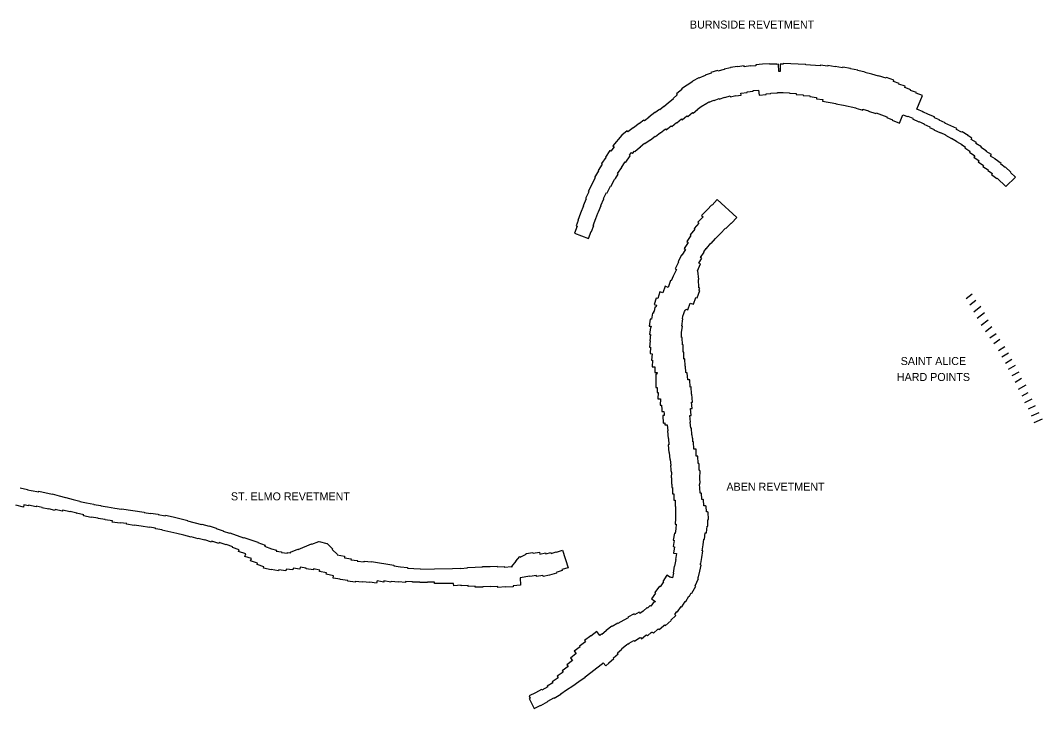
# Model space of a CAD drawing. Extents: x 2650582 to 3923188, y 277893 to 989177.
# Drawn here: x 3390842 to 3411271, y 583622 to 597381 of the extents above; entities that cross this region are included whole.
import ezdxf

# ---------------------------------------------------------------- set-up
doc = ezdxf.new("R2010")
doc.units = 0
doc.layers.add('Level 3', color=7, linetype='Continuous')

msp = doc.modelspace()

# ---------------------------------------------------------------- linework, layer by layer
at = {"layer": 'Level 3'}
for p, q in [((3409746, 591820), (3409864, 591911)), ((3409818, 591692), (3409940, 591791)), ((3409900, 591557), (3410040, 591668)), ((3409966, 591430), (3410109, 591539)), ((3410046, 591290), (3410186, 591392)), ((3410129, 591164), (3410259, 591264)), ((3410220, 591035), (3410345, 591120)), ((3410296, 590920), (3410415, 591006)), ((3410390, 590782), (3410518, 590864)), ((3410455, 590652), (3410590, 590738)), ((3410527, 590525), (3410659, 590607)), ((3410590, 590410), (3410730, 590488)), ((3410661, 590281), (3410805, 590354)), ((3410722, 590147), (3410851, 590227)), ((3410791, 590010), (3410943, 590097)), ((3410862, 589878), (3410986, 589939)), ((3410918, 589740), (3411062, 589812)), ((3410990, 589614), (3411131, 589682)), ((3411051, 589476), (3411201, 589541)), ((3411105, 589342), (3411271, 589412))]:
    msp.add_line(p, q, dxfattribs=at)
for points in [[(3405537, 596493), (3405539, 596476), (3405433, 596464), (3405432, 596470), (3405310, 596456), (3405308, 596471), (3405175, 596456), (3405175, 596460), (3405033, 596441), (3405033, 596436), (3404906, 596407), (3404907, 596398), (3404778, 596366), (3404775, 596379), (3404641, 596338), (3404645, 596325), (3404528, 596287), (3404530, 596282), (3404401, 596227), (3404400, 596230), (3404276, 596164), (3404279, 596157), (3404171, 596087), (3404170, 596089), (3404054, 596010), (3404058, 596001), (3403956, 595912), (3403970, 595895), (3403888, 595823), (3403894, 595816), (3403785, 595729), (3403787, 595727), (3403703, 595655), (3403700, 595658), (3403624, 595591), (3403615, 595603), (3403522, 595534), (3403519, 595537), (3403399, 595448), (3403403, 595442), (3403316, 595375), (3403304, 595389), (3403212, 595317), (3403209, 595321), (3403093, 595233), (3403091, 595236), (3402985, 595151), (3402970, 595171), (3402864, 595084), (3402861, 595086), (3402685, 594872)], [(3408290, 596159), (3408300, 596188), (3408153, 596239), (3408148, 596227), (3407995, 596271), (3407994, 596268), (3407859, 596307), (3407858, 596303), (3407721, 596339), (3407723, 596345), (3407576, 596380), (3407577, 596386), (3407431, 596415), (3407431, 596419), (3407278, 596448), (3407275, 596435), (3407129, 596461), (3407128, 596455), (3406979, 596478), (3406977, 596469), (3406829, 596485), (3406827, 596470), (3406538, 596492), (3406538, 596501), (3406089, 596517), (3406089, 596503), (3406028, 596504), (3406028, 596361), (3405997, 596361), (3405996, 596503), (3405957, 596502), (3405957, 596509), (3405816, 596505), (3405815, 596511), (3405676, 596506), (3405675, 596509), (3405537, 596493)], [(3410540, 594060), (3410729, 594245), (3410631, 594343), (3410635, 594347), (3410531, 594444), (3410525, 594438), (3410435, 594510), (3410444, 594522), (3410321, 594608), (3410325, 594615), (3410233, 594670), (3410251, 594697), (3410147, 594760), (3410153, 594768), (3410044, 594840), (3410052, 594852), (3409939, 594923), (3409948, 594937), (3409842, 595002), (3409860, 595029), (3409780, 595079), (3409782, 595081), (3409661, 595155), (3409654, 595145), (3409548, 595202), (3409556, 595217), (3409438, 595275), (3409437, 595272), (3409319, 595327), (3409322, 595334), (3409206, 595387), (3409209, 595393), (3409108, 595436), (3409114, 595451), (3408991, 595501), (3408992, 595503), (3408881, 595552), (3408883, 595556), (3408760, 595605), (3408869, 595877), (3408744, 595925), (3408750, 595940), (3408630, 595980), (3408635, 595994), (3408516, 596038), (3408524, 596064), (3408401, 596107), (3408405, 596119), (3408290, 596159)], [(3403014, 594685), (3403056, 594740), (3403078, 594722), (3403117, 594767), (3403120, 594762), (3403174, 594805), (3403232, 594851), (3403228, 594856), (3403318, 594928), (3403324, 594919), (3403429, 594996), (3403432, 594991), (3403531, 595066), (3403535, 595060), (3403634, 595137), (3403636, 595135), (3403736, 595210), (3403747, 595195), (3403849, 595271), (3403861, 595257), (3403957, 595337), (3403959, 595335), (3404053, 595412), (3404068, 595394), (3404164, 595475), (3404178, 595459), (3404275, 595542), (3404288, 595527), (3404372, 595599), (3404370, 595602), (3404449, 595657), (3404559, 595728), (3404604, 595751), (3404606, 595744), (3404703, 595786), (3404705, 595780), (3404806, 595820), (3404810, 595808), (3404919, 595846), (3404921, 595839), (3405030, 595870), (3405034, 595854), (3405139, 595879), (3405139, 595873), (3405246, 595889), (3405241, 595926), (3405365, 595940), (3405365, 595952), (3405485, 595964), (3405485, 595977), (3405594, 595988)], [(3405594, 595988), (3405606, 595884), (3405745, 595899), (3405744, 595913), (3405839, 595917), (3405839, 595927), (3405971, 595932), (3405970, 595940), (3406084, 595941), (3406084, 595937), (3406215, 595936), (3406215, 595924), (3406345, 595920), (3406344, 595903), (3406486, 595894), (3406485, 595882), (3406621, 595872), (3406620, 595858), (3406756, 595842), (3406752, 595815), (3406876, 595799), (3406871, 595768), (3407137, 595721), (3407136, 595715), (3407293, 595685), (3407294, 595689), (3407539, 595634), (3407536, 595624), (3407677, 595587), (3407682, 595604), (3407791, 595571), (3407789, 595564), (3407937, 595518), (3407942, 595532), (3408161, 595452), (3408156, 595439), (3408269, 595396), (3408266, 595389), (3408411, 595328)], [(3408411, 595328), (3408478, 595494), (3408574, 595458), (3408576, 595465), (3408679, 595424), (3408673, 595410), (3408799, 595355), (3408801, 595358), (3408904, 595314), (3408900, 595304), (3409017, 595252), (3409011, 595238), (3409102, 595199), (3409101, 595195), (3409228, 595134), (3409232, 595141), (3409333, 595090), (3409332, 595088), (3409451, 595023), (3409454, 595027), (3409553, 594970), (3409548, 594962), (3409655, 594901), (3409653, 594897), (3409727, 594853), (3409715, 594835), (3409820, 594765), (3409809, 594750), (3409919, 594675), (3409898, 594644), (3410001, 594572), (3409987, 594551), (3410092, 594480), (3410079, 594460), (3410186, 594392), (3410179, 594381), (3410268, 594321), (3410253, 594301), (3410354, 594218), (3410364, 594229), (3410540, 594060)], [(3402685, 594872), (3402708, 594855), (3402643, 594765), (3402625, 594777), (3402534, 594646), (3402540, 594642), (3402454, 594517), (3402467, 594508), (3402388, 594381), (3402394, 594376), (3402318, 594239), (3402329, 594232), (3402192, 593962), (3402203, 593956), (3402135, 593819), (3402148, 593812), (3402089, 593675), (3402093, 593674), (3402034, 593530), (3402037, 593528), (3401984, 593383), (3401990, 593381), (3401950, 593272), (3401970, 593265), (3401919, 593124)], [(3401919, 593124), (3402196, 593022), (3402247, 593163), (3402257, 593160), (3402300, 593278), (3402287, 593283), (3402339, 593423), (3402341, 593422), (3402383, 593530), (3402393, 593553), (3402449, 593678), (3402441, 593681), (3402505, 593816), (3402496, 593820), (3402557, 593941), (3402567, 593937), (3402634, 594066), (3402645, 594061), (3402718, 594199), (3402734, 594221), (3402791, 594310), (3402777, 594319), (3402859, 594438), (3402853, 594442), (3402928, 594553), (3402941, 594546), (3403031, 594672), (3403014, 594685)], [(3404183, 591597), (3404228, 591731), (3404293, 591709), (3404338, 591843), (3404370, 591832), (3404420, 591979), (3404404, 591985), (3404424, 592027), (3404396, 592041), (3404401, 592041), (3404396, 592199), (3404400, 592200), (3404378, 592373), (3404371, 592376), (3404435, 592511), (3404400, 592528), (3404458, 592625), (3404435, 592639), (3404506, 592749), (3404501, 592752), (3404550, 592823), (3404551, 592821), (3404639, 592925), (3404645, 592920), (3404734, 593021), (3404833, 593123), (3404836, 593121), (3404935, 593225), (3404941, 593218), (3405047, 593328), (3405051, 593324), (3405158, 593443), (3404765, 593798), (3404668, 593690), (3404664, 593694), (3404567, 593593), (3404565, 593595), (3404457, 593482), (3404485, 593455), (3404381, 593348), (3404402, 593328), (3404306, 593220), (3404324, 593204), (3404230, 593092), (3404243, 593081), (3404160, 592961), (3404190, 592941), (3404110, 592819), (3404134, 592803), (3404064, 592687), (3404057, 592691), (3403991, 592551), (3403995, 592549), (3403929, 592415), (3403954, 592403), (3403887, 592266), (3403889, 592265), (3403845, 592175)], [(3403845, 592175), (3403837, 592178), (3403791, 592043), (3403726, 592065), (3403681, 591932), (3403623, 591951), (3403580, 591821), (3403546, 591831), (3403506, 591701), (3403553, 591687), (3403542, 591645), (3403522, 591648), (3403508, 591559), (3403496, 591560), (3403493, 591526), (3403477, 591528), (3403457, 591405), (3403429, 591410), (3403407, 591271)], [(3404229, 589349), (3404232, 589349), (3404221, 589481), (3404246, 589483), (3404234, 589621), (3404265, 589623), (3404257, 589747), (3404273, 589748), (3404262, 589906), (3404257, 589905), (3404246, 590052), (3404229, 590050), (3404219, 590195), (3404180, 590192), (3404171, 590338), (3404146, 590337), (3404146, 590342), (3404144, 590342), (3404137, 590469), (3404128, 590469), (3404119, 590612), (3404102, 590610), (3404098, 590749), (3404090, 590748), (3404087, 590894), (3404072, 590893), (3404070, 591042), (3404053, 591042), (3404057, 591143), (3404075, 591268), (3404061, 591270), (3404080, 591415), (3404072, 591415), (3404082, 591469), (3404101, 591519), (3404104, 591518), (3404116, 591559), (3404126, 591584), (3404130, 591583), (3404142, 591611), (3404183, 591597)], [(3403407, 591271), (3403446, 591265), (3403443, 591239), (3403435, 591240), (3403418, 591101), (3403436, 591099), (3403423, 590975), (3403429, 590975), (3403418, 590850), (3403437, 590849), (3403428, 590719), (3403465, 590717), (3403458, 590587), (3403474, 590586), (3403470, 590457), (3403521, 590455), (3403519, 590341), (3403565, 590341), (3403564, 590307), (3403541, 590306), (3403543, 590181), (3403541, 590181), (3403543, 590041), (3403571, 590042), (3403567, 589940)], [(3403567, 589940), (3403585, 589940), (3403581, 589815), (3403633, 589813), (3403629, 589688), (3403654, 589687), (3403659, 589603), (3403663, 589603), (3403661, 589562), (3403703, 589560), (3403706, 589525), (3403705, 589483), (3403678, 589481), (3403691, 589331)], [(3403691, 589331), (3403718, 589333), (3403721, 589293), (3403770, 589298), (3403780, 589177), (3403775, 589176), (3403787, 589022)], [(3404422, 588229), (3404423, 588229), (3404425, 588378), (3404417, 588378), (3404416, 588397), (3404410, 588397), (3404407, 588440), (3404408, 588518), (3404402, 588518), (3404401, 588524), (3404385, 588523), (3404384, 588670), (3404347, 588669), (3404345, 588806), (3404301, 588806), (3404296, 588954), (3404284, 588953), (3404278, 589029), (3404273, 589029), (3404269, 589097), (3404262, 589097), (3404251, 589227), (3404239, 589226), (3404229, 589349)], [(3403787, 589022), (3403792, 589023), (3403803, 588898), (3403786, 588897), (3403800, 588740), (3403806, 588741), (3403819, 588600), (3403828, 588601), (3403840, 588479), (3403836, 588478), (3403842, 588412), (3403841, 588370), (3403846, 588370), (3403848, 588347), (3403852, 588347), (3403851, 588236), (3403854, 588236), (3403854, 588224), (3403853, 588106), (3403859, 588106)], [(3404431, 586495), (3404435, 586521), (3404439, 586520), (3404460, 586646), (3404458, 586646), (3404479, 586775), (3404470, 586777), (3404487, 586898), (3404487, 586898), (3404502, 587009), (3404512, 587008), (3404526, 587139), (3404552, 587136), (3404565, 587268), (3404580, 587268), (3404578, 587399), (3404596, 587401), (3404586, 587552), (3404573, 587551), (3404573, 587553), (3404556, 587553), (3404546, 587672), (3404534, 587671), (3404534, 587679), (3404504, 587679), (3404493, 587799), (3404477, 587797), (3404477, 587804), (3404463, 587804), (3404453, 587926), (3404442, 587925), (3404442, 587929), (3404427, 587929), (3404423, 588038), (3404421, 588038), (3404417, 588102), (3404420, 588102), (3404420, 588130), (3404426, 588130), (3404422, 588229)], [(3390834, 588038), (3390986, 588001), (3390985, 587996)], [(3390985, 587996), (3391057, 587983), (3391057, 587985), (3391207, 587957), (3391209, 587966), (3391474, 587907), (3391476, 587916), (3391619, 587877), (3391618, 587876), (3391745, 587842), (3391746, 587844), (3391897, 587805), (3391896, 587800), (3392031, 587770), (3392030, 587764), (3392160, 587738), (3392159, 587737), (3392312, 587707), (3392312, 587704), (3392448, 587681), (3392447, 587677), (3392581, 587658), (3392580, 587654), (3392727, 587632), (3392726, 587626), (3392859, 587608), (3392860, 587613), (3393318, 587547), (3393317, 587545), (3393444, 587524), (3393444, 587528), (3393596, 587511), (3393595, 587502), (3393736, 587477), (3393739, 587489), (3393895, 587455), (3393896, 587456), (3394185, 587384), (3394183, 587377), (3394463, 587305), (3394465, 587312), (3394612, 587269), (3394613, 587273), (3394756, 587227), (3394755, 587225), (3394896, 587176), (3394894, 587171), (3395023, 587127), (3395026, 587134)], [(3403859, 588106), (3403859, 588039), (3403875, 588039), (3403875, 587914), (3403903, 587914), (3403903, 587789), (3403925, 587789), (3403926, 587664), (3403937, 587664), (3403937, 587554), (3403934, 587554), (3403934, 587420), (3403928, 587311), (3403951, 587309), (3403939, 587215), (3403940, 587215), (3403925, 587124), (3403914, 587126), (3403889, 586987), (3403909, 586984), (3403887, 586861), (3403914, 586856), (3403893, 586732), (3403953, 586722)], [(3390900, 587648), (3390748, 587686)], [(3394809, 586924), (3394668, 586969), (3394662, 586952), (3394529, 586995), (3394527, 586988), (3394396, 587024), (3394394, 587018), (3394253, 587055), (3394252, 587052), (3394107, 587089), (3394106, 587087), (3393966, 587123), (3393965, 587120), (3393671, 587186), (3393673, 587197), (3393540, 587219), (3393541, 587229), (3393419, 587250), (3393418, 587243), (3393253, 587268), (3393254, 587271), (3393118, 587292), (3393116, 587282), (3392963, 587309), (3392965, 587320), (3392834, 587337), (3392833, 587329), (3392676, 587351), (3392680, 587376), (3392535, 587396), (3392536, 587404), (3392392, 587425), (3392392, 587428), (3392254, 587450), (3392253, 587444), (3392104, 587474), (3392109, 587498), (3391965, 587528), (3391966, 587532), (3391833, 587563), (3391830, 587555), (3391686, 587592), (3391679, 587568), (3391538, 587604), (3391532, 587585), (3391410, 587615), (3391408, 587606), (3391272, 587635), (3391274, 587641), (3391155, 587667), (3391153, 587659), (3391004, 587686), (3391002, 587676), (3390911, 587693), (3390900, 587648)], [(3395026, 587134), (3395302, 587039), (3395304, 587045), (3395588, 586946), (3395587, 586942), (3395730, 586890), (3395722, 586870), (3395861, 586818), (3395859, 586815), (3395959, 586790), (3395955, 586772), (3396059, 586756), (3396058, 586745), (3396178, 586730), (3396181, 586745), (3396248, 586736), (3396242, 586751), (3396389, 586810), (3396391, 586805), (3396660, 586918), (3396664, 586910), (3396807, 586960), (3396808, 586956), (3396810, 586960), (3396965, 586924), (3396963, 586916), (3396969, 586922), (3397082, 586819), (3397070, 586804), (3397178, 586701), (3397175, 586699), (3397322, 586672), (3397317, 586633), (3397450, 586614), (3397448, 586594), (3397576, 586583), (3397575, 586572), (3397710, 586559), (3397711, 586570), (3397858, 586554), (3397859, 586560), (3398308, 586487), (3398306, 586479), (3398441, 586459), (3398441, 586455), (3398577, 586441), (3398576, 586432), (3398702, 586426), (3398702, 586421), (3398837, 586415), (3398837, 586411), (3399118, 586413), (3399118, 586418), (3399479, 586426), (3399479, 586420), (3399634, 586432), (3399635, 586423), (3399777, 586435), (3399777, 586441)], [(3398535, 586144), (3398400, 586158), (3398398, 586148), (3398251, 586166), (3398248, 586152), (3398108, 586175), (3398102, 586151), (3397969, 586174), (3397960, 586129), (3397825, 586150), (3397825, 586145), (3397678, 586157), (3397677, 586151), (3397534, 586164), (3397532, 586152), (3397383, 586167), (3397384, 586181), (3397233, 586200), (3397234, 586207), (3397090, 586232), (3397098, 586278), (3396952, 586309), (3396958, 586335), (3396820, 586365), (3396825, 586392), (3396700, 586415), (3396696, 586394), (3396550, 586419), (3396552, 586431), (3396435, 586449), (3396427, 586408), (3396294, 586429), (3396288, 586396), (3396151, 586412), (3396146, 586378), (3396004, 586393), (3396000, 586378), (3395855, 586402), (3395852, 586394), (3395701, 586432), (3395706, 586455), (3395570, 586504), (3395577, 586527), (3395442, 586578), (3395458, 586620), (3395327, 586666), (3395344, 586713), (3395203, 586760), (3395214, 586795), (3395079, 586840), (3395084, 586858), (3394955, 586901), (3394953, 586895), (3394814, 586940), (3394809, 586924)], [(3400661, 586456), (3400673, 586458), (3400665, 586465), (3400748, 586568), (3400746, 586569), (3400824, 586666), (3400843, 586650), (3400845, 586652), (3400845, 586657), (3400859, 586660), (3400949, 586712), (3400948, 586720), (3401086, 586743), (3401089, 586727), (3401217, 586749), (3401223, 586710), (3401337, 586733), (3401340, 586715), (3401445, 586743), (3401450, 586726), (3401552, 586758), (3401555, 586749), (3401679, 586787), (3401787, 586439), (3401663, 586401), (3401668, 586383), (3401549, 586346), (3401553, 586327), (3401417, 586292), (3401290, 586266), (3401286, 586284), (3401158, 586261), (3401154, 586283), (3401026, 586261), (3401025, 586267), (3400828, 586233)], [(3403953, 586722), (3403934, 586604), (3403938, 586604), (3403916, 586467), (3403910, 586468), (3403886, 586328), (3403893, 586327), (3403874, 586234), (3403834, 586249), (3403832, 586244)], [(3399777, 586441), (3399928, 586448), (3399928, 586452), (3400080, 586455), (3400080, 586464), (3400233, 586465), (3400233, 586463), (3400372, 586469), (3400374, 586453), (3400508, 586464), (3400509, 586451), (3400660, 586463), (3400661, 586456)], [(3404248, 585939), (3404262, 585931), (3404342, 586069), (3404325, 586079), (3404396, 586220), (3404380, 586228), (3404383, 586228), (3404384, 586234), (3404389, 586232), (3404420, 586369), (3404419, 586370), (3404447, 586491), (3404431, 586495)], [(3400828, 586233), (3400838, 586090), (3400688, 586078), (3400689, 586059), (3400535, 586048), (3400534, 586053), (3400384, 586043), (3400382, 586060), (3400232, 586054), (3400232, 586061), (3400085, 586059), (3400085, 586051), (3399930, 586050), (3399929, 586072), (3399792, 586065), (3399790, 586083), (3399653, 586073), (3399652, 586089), (3399503, 586077), (3399499, 586125), (3399119, 586123), (3399119, 586150), (3398979, 586150), (3398979, 586146), (3398824, 586144), (3398823, 586151), (3398681, 586152), (3398680, 586156), (3398538, 586163), (3398535, 586144)], [(3403832, 586244), (3403762, 586288), (3403683, 586162), (3403693, 586156), (3403628, 586059), (3403613, 586069), (3403524, 585942), (3403538, 585932), (3403457, 585818)], [(3403943, 585482), (3403922, 585505), (3403963, 585563), (3403972, 585557), (3404048, 585665), (3404061, 585657), (3404130, 585765), (3404138, 585761), (3404203, 585872), (3404215, 585867), (3404248, 585939)], [(3403457, 585818), (3403533, 585765), (3403525, 585754), (3403511, 585765), (3403443, 585672), (3403429, 585685), (3403375, 585631), (3403367, 585640), (3403285, 585572), (3403288, 585567), (3403223, 585520), (3403206, 585550), (3403118, 585499), (3403107, 585519), (3402984, 585447), (3402990, 585437), (3402905, 585387), (3402902, 585392), (3402785, 585325), (3402783, 585329), (3402667, 585263), (3402659, 585272), (3402549, 585181), (3402552, 585178), (3402462, 585104), (3402456, 585111), (3402420, 585081)], [(3402980, 584917), (3402983, 584913), (3403011, 584933), (3403103, 584986), (3403115, 584969), (3403220, 585045), (3403226, 585034), (3403238, 585041), (3403258, 585019), (3403340, 585093), (3403343, 585088), (3403357, 585096), (3403374, 585077), (3403457, 585151), (3403463, 585143), (3403474, 585151), (3403493, 585130), (3403583, 585211), (3403587, 585206), (3403596, 585214), (3403607, 585202), (3403692, 585279), (3403693, 585277), (3403712, 585296), (3403731, 585275), (3403847, 585381), (3403840, 585389), (3403943, 585482)], [(3402420, 585081), (3402359, 585160), (3402243, 585071), (3402239, 585077), (3402116, 584982), (3402134, 584958), (3402018, 584867), (3402026, 584858), (3401912, 584770), (3401950, 584720), (3401837, 584633), (3401878, 584581), (3401763, 584499), (3401788, 584465), (3401667, 584378), (3401686, 584352), (3401567, 584270), (3401589, 584239), (3401468, 584155), (3401481, 584136), (3401372, 584073), (3401382, 584055), (3401262, 583990), (3401255, 584002), (3401135, 583937), (3401134, 583940), (3401009, 583880)], [(3402490, 584537), (3402541, 584477), (3402604, 584531), (3402601, 584536), (3402705, 584622), (3402694, 584635), (3402791, 584718), (3402775, 584736), (3402862, 584809), (3402856, 584815), (3402962, 584902), (3402959, 584905), (3402980, 584917)], [(3401009, 583880), (3401031, 583833), (3401010, 583823), (3401107, 583622), (3401242, 583688), (3401244, 583684), (3401386, 583762), (3401382, 583769), (3401506, 583836), (3401508, 583832), (3401645, 583911), (3401643, 583915), (3401758, 583996), (3401758, 583996), (3401880, 584080), (3401882, 584078), (3402003, 584164), (3402005, 584162), (3402131, 584253), (3402127, 584257), (3402240, 584344), (3402242, 584341), (3402365, 584436), (3402364, 584436), (3402477, 584525), (3402476, 584526), (3402490, 584537)]]:
    msp.add_lwpolyline(points, dxfattribs=at)

# ---------------------------------------------------------------- texts
for s, p in [('BURNSIDE REVETMENT', (3404223, 597218)), ('SAINT ALICE', (3408435, 590491)), ('HARD POINTS', (3408359, 590172)), ('ABEN REVETMENT', (3404953, 587978)), ('ST. ELMO REVETMENT', (3395049, 587785))]:
    msp.add_text(s, height=160, dxfattribs=at).set_placement(p)

doc.saveas('drawing.dxf')
